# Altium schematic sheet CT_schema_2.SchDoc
size 368 x 207 mm
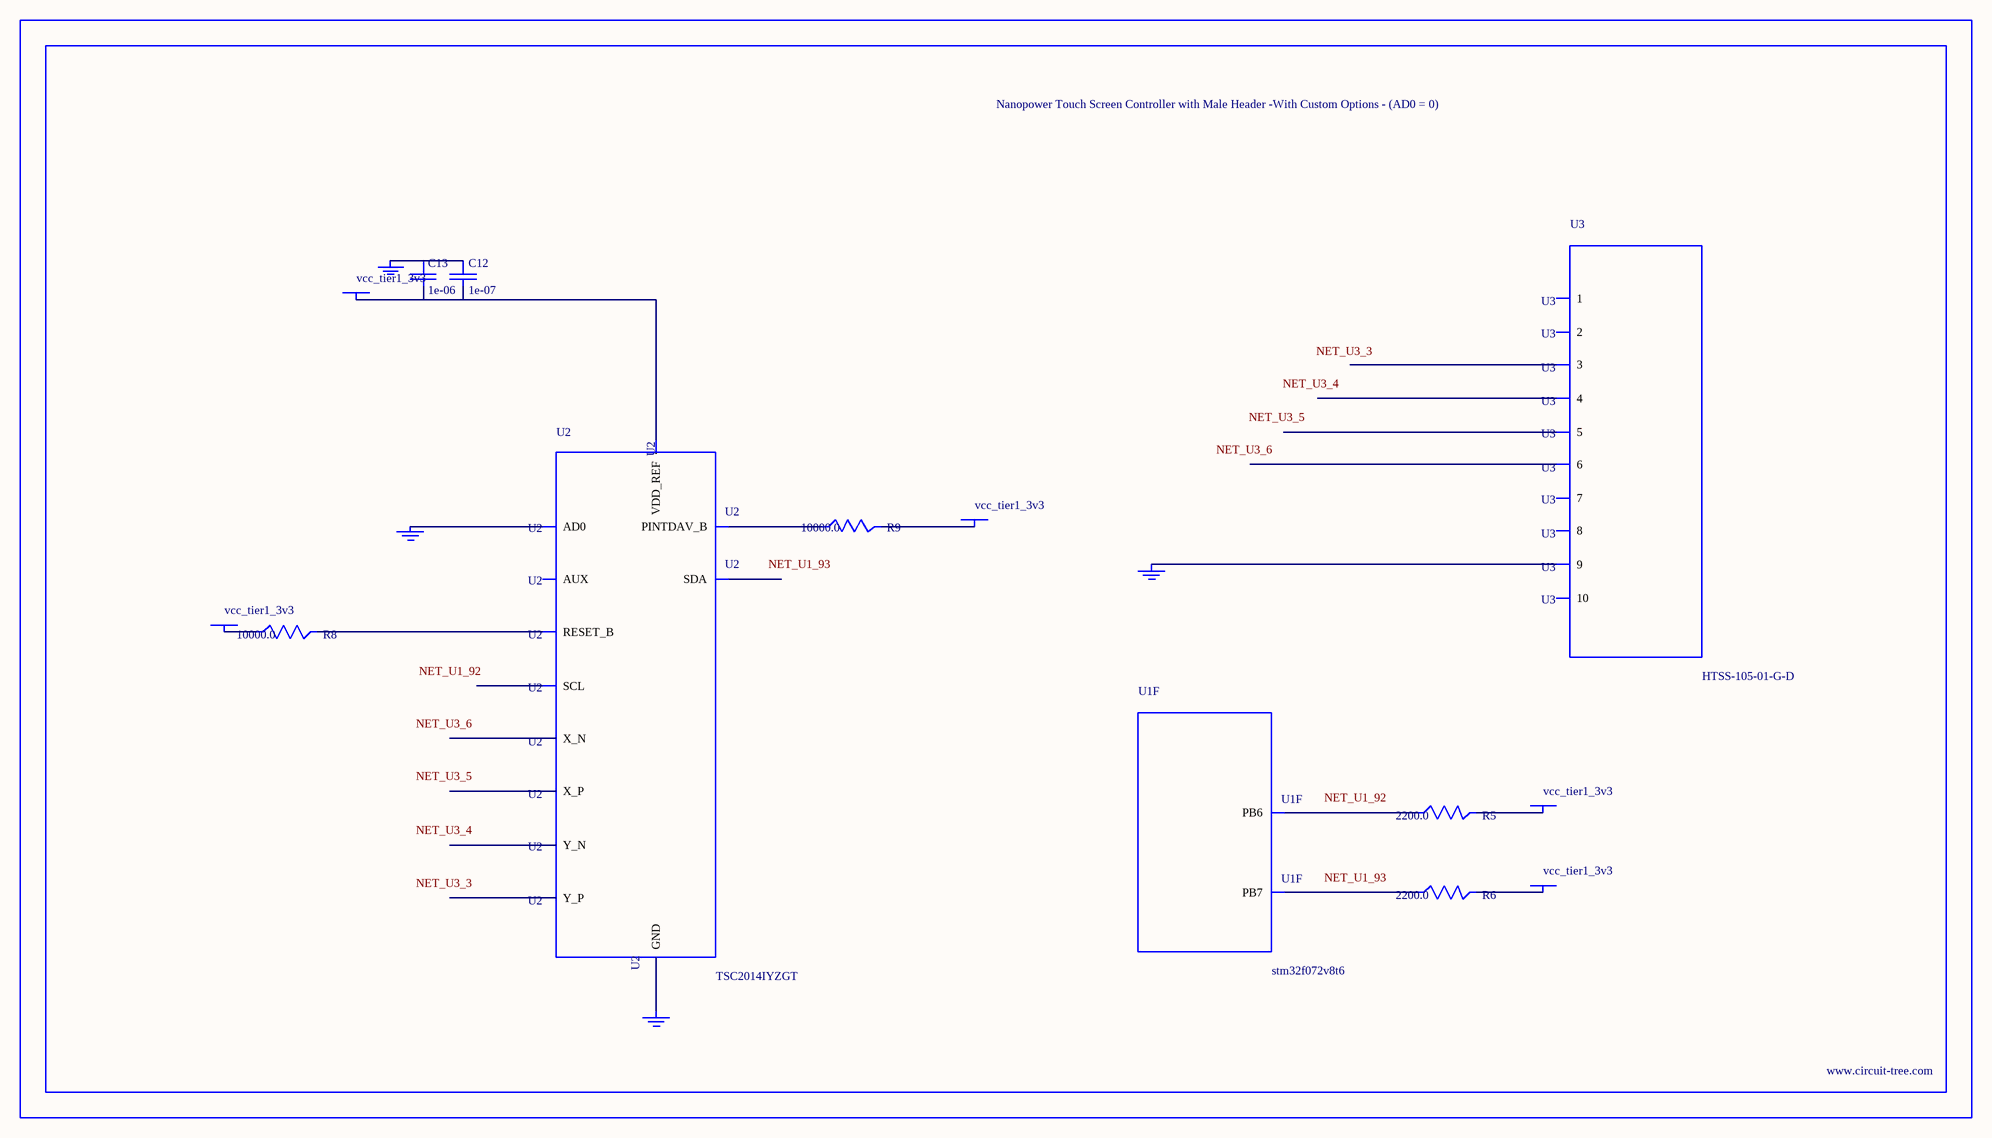
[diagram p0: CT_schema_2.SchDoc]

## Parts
BORDER1  (no value)
C12  1e-07  [C0402]
C13  1e-06  [C0603]
GND_INSTANCE_1_0  (no value)
GND_INSTANCE_1_1  (no value)
GND_INSTANCE_1_2  (no value)
GND_INSTANCE_1_3  (no value)
POWER_INSTANCE_1_0  vcc_tier1_3v3
POWER_INSTANCE_1_1  vcc_tier1_3v3
POWER_INSTANCE_1_2  vcc_tier1_3v3
POWER_INSTANCE_1_3  vcc_tier1_3v3
POWER_INSTANCE_1_4  vcc_tier1_3v3
R5  2200.0  [R0603]
R6  2200.0  [R0603]
R8  10000.0  [R0603]
R9  10000.0  [R0603]
U1  stm32f072v8t6  [LQFP100]  (part F of 9)
U2  TSC2014IYZGT  [TSC2014IYZGT]
U3  HTSS-105-01-G-D  [HTSS-105-01-G-D]

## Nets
NetC12_1: C12.1 C13.1 GND_INSTANCE_1_0.0(GND)
NetC12_2: C12.2 C13.2 POWER_INSTANCE_1_2.0(PWR) U2.A2(VDD_REF)
NetGND_INSTANCE_1_1_0: GND_INSTANCE_1_1.0(GND) U2.B2(AD0)
NetGND_INSTANCE_1_2_0: GND_INSTANCE_1_2.0(GND) U2.D2(GND)
NetGND_INSTANCE_1_3_0: GND_INSTANCE_1_3.0(GND) U3.9
NetPOWER_INSTANCE_1_0_0: POWER_INSTANCE_1_0.0(PWR) R8.1
NetPOWER_INSTANCE_1_1_0: POWER_INSTANCE_1_1.0(PWR) R9.2
NetPOWER_INSTANCE_1_3_0: POWER_INSTANCE_1_3.0(PWR) R5.2
NetPOWER_INSTANCE_1_4_0: POWER_INSTANCE_1_4.0(PWR) R6.2
NetR5_1: R5.1 U1.92(PB6)
NetR6_1: R6.1 U1.93(PB7)
NetR8_2: R8.2 U2.C2(RESET_B)
NetR9_1: R9.1 U2.B1(PINTDAV_B)

Not connected (* = marked no-connect by the designer): U2 A1(AUX) A3(X_P) B3(Y_P) C1(SDA) C3(X_N) D1(SCL) D3(Y_N); U3 1 2 3 4 5 6 7 8 10

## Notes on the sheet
- Labels drawn without touching a wire or pin: NET_U1_92, NET_U1_93, NET_U3_3, NET_U3_4, NET_U3_5, NET_U3_6

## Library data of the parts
BORDER1 = BORDER_PAGE1
C12 = C0402C104K3RACTU
C13 = C0603C105K3RACTU
GND_INSTANCE_1_0-GND_INSTANCE_1_3 = GND
POWER_INSTANCE_1_0-POWER_INSTANCE_1_4 = PWR
R5 R6 = RC0603JR-072K2L
R8 R9 = RC0603JR-0710KL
